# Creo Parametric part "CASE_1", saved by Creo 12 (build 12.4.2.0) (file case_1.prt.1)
Units: Custom; MM, KILOGRAM, SECS

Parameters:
  PTC_WM_ITERATION = "0"
  PTC_WM_VERSION = "-.0"
  PTC_WM_LIFECYCLE_STATE = "In Work"
  PTC_WM_LIFECYCLE = "MO_CADDocument"
  PTC_WM_CREATED_BY = "Maximilian Roepper (Z0017RMS: MO)"
  PTC_WM_CREATED_ON = "18-Sep-26 11:36:42 AM"
  PTC_WM_MODIFIED_BY = "Maximilian Roepper (Z0017RMS: MO)"
  PTC_WM_MODIFIED_ON = "18-Sep-26 11:36:46 AM"
  PDMLINKNUMBER = "PDM000071455243"
  PTC_WM_NAME = "case_1.prt"
  PTC_WM_NUMBER = "PDM000071455243"

Other parameters: WEIGHT, WEIGHT_FACTOR, WEIGHT_ADD, _MASS_TEMP, _DIFF_TEMP, MC_ERRORS, SUPPLIER

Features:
  1. coordinate system
  2. datum plane "PRT_YZ"
  3. datum plane "PRT_XY"
  4. datum plane "PRT_XZ"
  5. coordinate system
  6. datum axis
  7. datum axis
  8. datum axis
  9. coordinate system
  10. imported feature
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
Other named items: PRT, SIEMENS_MO, DRW_VIEW_ORG, PRT_X, PRT_Y, PRT_Z, CS0, ROUGH_GROB

Layers: 00_STD_CSYS-KSYS, 01_STD_PLANES-EBENEN, 02_STD_AXES-ACHSEN, 03_STD_CSYS-KSYS, 24_IMPORT_FEAT-IMPORT_KE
